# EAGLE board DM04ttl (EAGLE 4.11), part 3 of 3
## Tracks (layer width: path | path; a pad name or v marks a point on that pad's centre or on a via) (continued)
VCC  (via drill 0.61) (continued)
  Bottom 0.635: RN17.1 90.17,68.58 v71.75,68.58 69.85,68.58 IC7.20 | C7.1 66.67,71.12 64.77,73.03 61.59,73.03 57.15,68.58 RN19.1 54.61,68.58 v50.8,68.58 v33.02,68.58 | v56.52,111.76 57.78,113.03 v66.67,113.03 68.58,114.94 v71.75,114.94 | IC34.14 69.22,155.57 69.85,156.21 70.48,156.21 C34.1 | RN7.1 90.17,139.7 69.85,139.7 IC21.20 | IC2.14 28.57,59.05 29.21,59.69 29.84,59.69 C2.1 | IC5.16 33.66,74.3 34.29,74.93 34.92,74.93 C5.1 | IC3.16 31.11,13.34 31.75,13.97 32.38,13.97 C3.1 | IC1.14 28.57,28.57 29.21,29.21 29.84,29.21 C1.1 | IC4.16 31.11,43.81 31.75,44.45 32.38,44.45 C4.1 | C31.1 70.48,186.69 69.85,186.69 69.22,186.06 IC31.16 68.58,186.69 67.31,187.96 40.01,187.96 38.73,186.69 C38.1 | SV1.1 45.09,172.72 43.81,171.45 38.73,171.45 C37.1 | RN9.1 54.61,139.7 34.29,139.7 IC19.16 | C18.1 31.11,109.22 21.59,118.75 16.51,118.75 C97.+ | C21.1 66.67,142.24 64.77,144.15 34.29,144.15 32.38,142.24 C19.1
WCOV0\
  Bottom 0.254: 144.15,105.41 153.03,105.41 154.31,104.14 161.29,104.14 RN2.3 | 144.15,105.41 27.94,105.41 26.67,104.14 IC18.2 | 144.15,105.41 149.22,110.49 150.5,110.49 151.76,109.22 DATA0.BB
WCOV1\  (via drill 0.61)
  Top 0.254: v104.14,78.74 107.95,82.55 107.95,106.05 v107.31,106.68 | RN6.3 125.73,104.14 118.75,104.14 117.47,105.41 115.57,105.41 115.57,107.31 116.84,108.58 DATA1.BB
  Bottom 0.254: v104.14,78.74 78.11,78.74 76.83,80.01 38.1,80.01 26.67,91.44 IC18.7 | v107.31,106.68 108.58,107.95 114.94,107.95 116.2,109.22 DATA1.BB
WCOV2\  (via drill 0.61)
  Top 0.254: v38.1,106.68 38.1,93.98 33.66,89.53 IC18.9 | v88.27,106.68 88.27,106.05 90.17,104.14 RN8.3
  Bottom 0.254: v38.1,106.68 41.91,110.49 79.38,110.49 80.64,109.22 DATA2.BB 81.92,109.22 85.72,109.22 v88.27,106.68
WCOV3\  (via drill 0.61)
  Top 0.254: v46.99,102.87 46.99,107.31 45.72,108.58 DATA3.BB
  Bottom 0.254: IC18.15 34.29,104.14 35.56,102.87 v46.99,102.87 48.26,102.87 49.53,104.14 54.61,104.14 RN10.3
WCOV\  (via drill 0.61)
  Top 0.254: IC17.8 17.14,89.53 15.88,90.81 15.88,94.61 17.14,95.89 IC17.11 18.41,97.16 19.68,98.42 v19.68,140.97 | IC17.2 9.53,100.97 8.26,99.69 8.26,95.89 9.53,94.61 IC17.5 | v219.71,139.06 219.71,111.12 218.44,109.86 DATA.BB
  Bottom 0.254: IC17.5 11.43,93.98 13.97,96.52 16.51,96.52 IC17.11 | v219.71,139.06 216.53,142.24 182.88,142.24 176.53,135.89 173.99,135.89 171.45,138.43 166.37,138.43 163.83,140.97 136.53,140.97 133.99,143.51 118.75,143.51 116.2,140.97 v19.68,140.97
